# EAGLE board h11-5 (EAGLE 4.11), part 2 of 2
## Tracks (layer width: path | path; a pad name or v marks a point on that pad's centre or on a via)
+12V  (via drill 0.61)
  Top 0.635: v21.59,97.79 24.13,101.6 v31.75,101.6 | 174.63,109.22 176.53,107.31 176.53,100.33 IC24.14 | 174.63,109.22 176.53,111.12 176.53,114.94 178.44,116.84 187.33,116.84 R3.2 | Q5.3 174.63,109.22 | v182.88,49.53 195.58,49.53 198.12,52.07 C16.+ 198.12,123.19 189.87,123.19 R4.2
  Bottom 0.635: EDGE$.BD2 20.96,83.82 22.86,85.72 22.86,96.52 v21.59,97.79 | v31.75,101.6 31.75,129.54 45.72,129.54 | 109.22,129.54 187.33,129.54 R3.2 R4.2 | 109.22,129.54 45.72,129.54 | 45.72,129.54 C18.+ | R11.1 Q5.3 | 109.22,129.54 C17.+ | R24.1 R22.1 182.88,64.77 v182.88,49.53
-12V
  Bottom 0.635: W30.2 C8.- D5.A 184.15,97.79 184.15,87.63 | CL3.1 179.07,5.08 179.07,17.78 180.34,20.32 180.34,33.02 181.61,33.02 181.61,43.18 185.42,46.99 | 185.42,46.99 185.42,53.34 184.15,55.24 184.15,65.41 185.42,68.58 185.42,80.01 184.15,81.28 184.15,87.63 | 184.15,87.63 R2.2 | 185.42,46.99 CL2.2
-12V_EIA
  Top 0.406: W30.1 177.8,88.9 171.45,88.9 170.18,90.17 170.18,91.44 168.91,92.71 168.91,100.33 IC24.1
A1R
  Top 0.406: IC18.5 IC18.10 139.7,45.72 139.7,41.91 125.73,41.91 124.46,40.64 IC19.9 | IC12.3 114.3,19.05 116.84,16.51 IC12.11
  Bottom 0.406: IC12.11 116.84,16.51 116.84,25.4 119.38,27.94 IC19.9
A1R\  (via drill 0.61)
  Top 0.406: v73.66,35.56 74.93,36.2 81.28,36.2 83.82,37.47 88.27,37.47 89.54,36.83 96.52,36.83 99.06,39.37 v107.95,39.37 110.49,40.64 IC19.8 | IC26.13 135.26,97.79 133.35,101.6 127,101.6 127,99.06 123.19,99.06 119.38,93.98 113.03,93.98 | v111.76,93.98 113.03,93.98 | 113.03,93.98 114.3,93.98
  Bottom 0.406: IC10.9 69.85,11.43 69.85,16.51 76.2,20.32 76.2,24.13 76.2,33.02 v73.66,35.56 | v107.95,39.37 107.95,60.96 109.22,64.77 109.22,72.39 107.95,73.66 107.95,86.36 111.76,87.63 v111.76,93.98
A2R  (via drill 0.61)
  Top 0.406: IC18.9 134.62,43.18 132.08,44.45 123.19,44.45 121.92,43.18 IC19.10 | v121.92,54.61 107.32,54.61 106.05,55.88 100.97,55.88 98.43,53.34 92.71,53.34 91.44,52.07 85.09,52.07 83.19,55.88 78.11,55.88 73.66,53.34 64.77,53.34 63.5,52.07 IC8.1
  Bottom 0.406: v121.92,54.61 121.92,43.18 IC19.10 116.84,43.18 116.84,27.94 115.57,26.67 115.57,15.24 116.84,13.97 118.11,13.97 | 118.11,13.97 118.75,13.97 | 118.11,13.97 IC12.10
A2R\
  Top 0.406: IC19.11 121.29,45.72 121.92,48.26 IC18.4
  Bottom 0.406: IC19.11 115.57,45.72 115.57,36.83 114.3,35.56 114.3,16.51 113.03,16.51 | 113.03,16.51 112.4,16.51 | IC12.4 113.03,16.51
A3
  Bottom 0.406: IC5.15 A3.2 R32.2
A4
  Bottom 0.406: IC5.23 A4.2 R31.2
A5
  Bottom 0.406: R29.2 A5.2 IC5.17
A6
  Bottom 0.406: IC5.19 A6.2 R28.2
A7
  Bottom 0.406: IC5.21 A7.2 R27.2
A8
  Bottom 0.406: A8.2 R26.2 IC5.9
A9
  Bottom 0.406: IC5.7 R25.2 A9.2
A10
  Bottom 0.406: A10.2 R23.2 IC5.5
A11
  Bottom 0.406: A11.2 R21.2 IC5.3
A12
  Bottom 0.406: A12.2 R19.2
  Bottom 0.635: R19.2 IC5.1
AMTCH  (via drill 0.61)
  Top 0.406: IC5.13 75.57,99.06 v74.93,98.42 | v88.9,12.7 80.65,12.7 78.74,15.24 72.39,15.24 | 72.39,15.24 64.77,15.24 63.5,16.51 IC10.4 | 72.39,15.24 R41.1
  Bottom 0.406: v88.9,12.7 87.63,13.97 87.63,36.2 83.82,40.01 83.82,81.28 82.55,82.55 82.55,87.63 74.93,93.98 v74.93,98.42
BBS7\  (via drill 0.61)
  Top 0.406: IC2.11 33.02,7.62 21.59,7.62 19.05,10.16 19.05,26.67 19.69,27.94 19.69,38.1 23.5,38.1 23.5,41.91 v22.23,42.55
  Bottom 0.406: EDGE$.AP2 7.62,41.91 v22.23,42.55
BDAL0\
  Top 0.406: IC3.11 48.26,74.93 46.36,73.03 31.12,73.03 31.12,76.2 29.21,77.47 IC4.9
  Bottom 0.406: EDGE$.AU2 26.04,54.61 26.04,59.69 27.94,61.59 27.94,72.39 24.13,72.39 24.13,77.47 IC4.9
BDAL1\
  Top 0.406: IC3.13 46.99,80.01 45.72,81.28 30.48,81.28 29.21,82.55 IC4.7
  Bottom 0.406: EDGE$.AV2 24.77,58.42 24.77,60.96 26.67,62.87 26.67,71.12 22.86,71.12 22.86,82.55 IC4.7
BDAL2\  (via drill 0.61)
  Top 0.406: v21.59,86.36 24.13,81.28 29.21,81.28 31.75,77.47 IC4.12 36.83,77.47 40.64,80.01 IC3.8
  Bottom 0.406: v21.59,86.36 16.82,86.69 7.62,87 EDGE$.BE2
BDAL3\  (via drill 0.61)
  Top 0.406: v21.59,88.9 24.13,83.82 30.48,83.82 31.75,82.55 IC4.14 36.83,82.55 40.64,85.09 IC3.6
  Bottom 0.406: v21.59,88.9 16.79,89.89 7.62,90.17 EDGE$.BF2
BDAL4\  (via drill 0.61)
  Top 0.406: v21.59,91.44 24.13,88.9 29.21,88.9 31.75,87.63 IC4.16 36.83,87.63 40.64,90.17 IC3.4
  Bottom 0.406: v21.59,91.44 16.82,93.04 7.62,93.34 EDGE$.BH2
BDAL5\  (via drill 0.61)
  Top 0.406: v21.59,93.98 29.21,93.98 31.12,92.71 IC4.18
  Bottom 0.406: v21.59,93.98 16.84,96.19 7.62,96.52 EDGE$.BJ2 | IC4.18 36.83,92.71 40.64,95.25 IC3.2
BDAL6\
  Top 0.406: IC3.15 49.53,85.09 44.45,88.9 40.64,88.9 36.83,86.36 31.75,86.36 29.21,87.63 IC4.5
  Bottom 0.406: IC4.5 24.13,87.63 24.13,99.06 23.83,99.36 7.62,99.06 EDGE$.BK2
BDAL7\
  Top 0.406: IC3.17 46.36,90.17 45.09,91.44 29.85,91.44 29.21,92.71 IC4.3
  Bottom 0.406: IC4.3 29.21,92.71 29.21,99.06 26.67,101.6 17.78,101.6 15.57,102.54 7.62,102.87 EDGE$.BL2
BDAL8\  (via drill 0.61)
  Top 0.406: v22.86,105.41 29.21,105.41 31.75,104.14 IC1.11
  Bottom 0.406: EDGE$.BM2 22.53,105.74 v22.86,105.41
BDAL9\
  Bottom 0.406: EDGE$.BN2 26.34,108.89 IC1.8
BDAL10\
  Bottom 0.406: EDGE$.BP2 23.19,112.09 25.4,114.3 IC1.6
BDAL11\
  Bottom 0.406: EDGE$.BR2 21.26,115.24 25.4,119.38 IC1.4
BDAL12\
  Bottom 0.406: EDGE$.BS2 19.36,118.42 25.4,124.46 IC1.2
BDAL15\  (via drill 0.61)
  Top 0.406: v19.05,120.65 19.05,100.33 16.51,98.42 16.51,78.74 v17.15,78.11 | IC9.11 48.26,16.51 45.72,17.78 29.85,17.78 29.85,25.4 25.4,25.4 24.77,26.04 24.77,32.38 26.04,34.29 26.04,45.72 22.86,48.9 v22.86,63.5
  Bottom 0.406: v22.86,63.5 22.86,64.77 17.78,68.58 17.78,77.47 v17.15,78.11 | EDGE$.BV2 19.05,128.27 v19.05,120.65
BDCOK
  Top 0.406: IC1.13 31.75,109.22 29.21,107.95 20.96,107.95 20.96,100.33 17.78,97.79 17.78,83.82 19.05,81.28 19.05,73.66 7.62,73.66
  Top 0.635: EDGE$.BA1 7.62,73.66
BDIN\
  Bottom 0.406: IC2.8 24.77,13.97 24.77,20.32 22.86,22.86 7.62,22.86 EDGE$.AH2
BDMG
  Bottom 0.406: EDGE$.AS2 16.51,48.26 16.51,45.72 7.62,45.72 EDGE$.AR2
BDOUT\  (via drill 0.61)
  Top 0.406: IC2.13 32.39,13.97 29.85,12.7 22.86,12.7 v20.96,10.79
  Bottom 0.406: v20.96,10.79 15.24,16.51 7.62,16.51 EDGE$.AE2
BHALT\
  Top 0.406: H1.1 19.05,42.55 7.62,41.91
  Top 0.635: EDGE$.AP1 7.62,42.19 7.62,41.91
BIAKI\
  Bottom 0.406: EDGE$.AM2 19.05,35.56 19.05,25.4 22.86,25.4 IC2.2
BIAKO\  (via drill 0.61)
  Top 0.406: IC9.3 39.37,19.05 38.1,20.32 31.75,20.32 v31.75,34.29 | R34.2 20.96,15.24 20.96,35.56 R35.2
  Bottom 0.406: v31.75,34.29 25.4,34.29 25.4,36.83 R35.2 19.05,36.83 17.78,39.37 7.62,39.37 EDGE$.AN2
BINIT\
  Bottom 0.406: EDGE$.AT2 20.32,52.07 20.32,47.62 27.94,41.27 33.66,41.27 36.2,38.73 36.2,19.05 IC2.15
BIRQ4\  (via drill 0.61)
  Top 0.406: IC9.8 47.63,8.89 45.09,10.16 38.74,10.16 37.47,8.89 37.47,6.35 21.59,6.35 17.78,10.16 v17.78,30.48
  Bottom 0.406: EDGE$.AL2 16.51,31.75 v17.78,30.48
BRPLY
  Top 0.406: IC14.6 145.42,11.43 142.24,8.89 142.24,5.71 107.95,5.71 107.95,11.43 IC11.9 90.17,11.43 87.63,10.16 65.41,10.16 62.23,15.24 57.15,15.24 52.07,12.7 47.63,12.7 46.36,13.97 IC9.5
  Bottom 0.406: IC11.9 IC11.10
BRPLY\  (via drill 0.61)
  Top 0.406: IC9.6 38.1,11.43 36.83,10.16 v23.5,10.16
  Bottom 0.406: v23.5,10.16 23.5,19.68 22.86,20.32 7.62,20.32 EDGE$.AF2
BSYNC\
  Bottom 0.406: EDGE$.AJ2 16.51,26.04 17.78,26.04 17.78,24.13 IC2.4
BUF  (via drill 0.61)
  Top 0.406: IC6.15 64.77,77.47 62.87,76.2 55.88,76.2 v54.61,74.93 | IC26.11 134.62,92.71 132.08,93.98 125.1,93.98 122.56,90.81 100.97,90.81 99.06,90.17 95.89,90.17 94.62,91.44 90.81,91.44 90.17,90.81 57.15,90.81 v55.88,90.17
  Bottom 0.406: IC7.15 50.8,52.07 52.07,53.34 52.07,55.88 50.8,57.15 50.8,71.12 v54.61,74.93 54.61,82.55 55.88,83.82 v55.88,90.17
BUF\  (via drill 0.61)
  Top 0.406: IC8.15 69.85,49.53 71.12,50.8 101.6,50.8 103.51,52.07 v124.46,52.07 | IC21.8 132.72,62.23 132.08,63.5 127.64,63.5 v124.46,62.23
  Bottom 0.406: v124.46,52.07 v124.46,62.23 | IC8.15 69.85,49.53 69.85,46.99 72.39,46.99 72.39,36.83 77.47,36.83 77.47,19.05 71.12,15.24 71.12,8.89 IC10.8
BUFDIN  (via drill 0.61)
  Top 0.406: v53.34,30.48 53.98,31.11 76.84,31.11 78.11,32.38 85.73,32.38 87.63,33.66 110.49,33.66 112.4,34.92 139.7,34.92 v140.97,35.56
  Bottom 0.406: v53.34,30.48 53.34,19.05 IC9.12 | v140.97,35.56 140.97,52.07 139.7,53.34 139.7,67.31 IC21.10
BUSY
  Top 0.406: IC24.8 180.34,85.09 182.88,87.63 182.88,92.71 184.79,95.25 191.14,95.25 192.41,96.52 SV1.10
CLK0  (via drill 0.61)
  Top 0.406: IC20.17 87,46.99 v87.63,47.62 | IC20.40 v87.63,87.63 | v79.38,107.95 91.44,107.95 91.44,102.87 102.87,102.87 105.41,105.41 105.41,121.92 135.89,121.92 135.89,116.2 142.88,116.2 142.88,109.86 IC27.10 155.58,109.86 155.58,107.31 163.83,107.31 163.83,92.08 163.2,90.81 163.2,85.09 IC25.8
  Bottom 0.406: v87.63,87.63 v87.63,47.62 | v79.38,107.95 80.01,106.68 80.01,96.52 85.09,92.08 92.08,92.08 95.25,89.53 IC20.40
CTS
  Top 0.406: IC23.13 177.8,74.93 177.8,78.74 188.6,78.74 191.77,83.82 SV1.15
  Bottom 0.406: SV1.15 SV1.14
CTS\
  Top 0.406: IC23.11 172.72,69.85 170.18,68.58 163.83,68.58 161.29,71.12 154.31,71.12 151.77,73.66 141.61,73.66 139.07,71.12 135.26,71.12 133.35,67.31 IC21.5
DIN\  (via drill 0.61)
  Top 0.406: IC4.1 29.21,97.79 31.75,95.25 IC4.19 37.47,95.25 39.37,96.52 66.68,96.52 67.95,95.25 90.17,95.25 93.98,99.06 106.05,99.06 109.86,92.08 114.94,92.08 | v140.97,92.08 139.07,93.98 134.62,93.98 132.08,95.25 IC26.3 124.46,95.25 121.92,92.08 114.94,92.08 | 114.94,92.08 114.3,92.08 | v142.88,64.77 IC21.9
  Bottom 0.406: v142.88,64.77 142.88,72.39 140.97,74.3 v140.97,92.08
DR0  (via drill 0.61)
  Top 0.406: v91.44,41.91 IC20.19 | IC8.14 76.2,46.99 v77.47,48.26
  Bottom 0.406: v77.47,48.26 77.47,43.18 78.74,41.91 IC20.19 | IC11.12 93.98,19.05 93.98,26.67 92.71,27.94 92.71,40.64 v91.44,41.91
DSR  (via drill 0.61)
  Top 0.406: IC21.4 127,69.85 123.83,66.67 106.05,66.67 106.05,63.5 v73.66,63.5 | IC8.2 63.5,49.53 64.77,48.26 v72.39,48.26
  Bottom 0.406: v73.66,63.5 73.66,54.61 72.39,52.07 v72.39,48.26
DSR\
  Top 0.406: IC23.8 172.09,62.23 170.18,66.04 146.05,66.04 143.51,63.5 134.62,63.5 132.08,64.77 IC21.6
DSREIA
  Top 0.406: IC23.10 177.8,67.31 177.8,69.85 190.5,69.85 190.5,77.47 191.77,78.74 SV1.17
EPS
  Top 0.406: IC20.39 98.43,85.09 99.06,84.45 EPS.2
FE0
  Top 0.406: IC20.14 78.11,54.61 73.66,52.07 71.12,52.07 69.85,50.8 58.42,50.8 55.25,53.34 39.37,53.34 38.74,53.98 34.29,53.98 34.29,42.55 Q1.2
GND  (via drill 0.61, 0.81 pad 1.27)
  Top 0.635: EDGE$.BT1 14.91,121.59 16.6,121.58 | 16.6,121.58 21.34,127 IC1.1 28.7,127 31.07,124.46 IC1.19 40.64,124.46 C18.- 40.64,128.27 57.15,128.27 | 16.6,121.58 16.6,105.74 | 16.6,105.74 EDGE$.BM1 | 16.6,105.74 v16.6,104.14 | v24.13,68.58 24.13,74.93 IC4.10 29.21,74.93 29.21,71.12 v30.48,70.48 33.66,69.22 V3.1 | 57.15,128.27 57.15,124.46 A12.1 | V7.1 V6.1 | 15.88,26.67 EDGE$.AJ1 | 15.88,26.67 15.88,36.2 7.62,36.2 EDGE$.AM1 | IC25.4 IC25.11 | IC9.7 41.91,6.99 59.69,6.99 | 59.69,6.99 72.39,6.99 74.93,8.89 IC11.7 | 59.69,6.99 IC10.7 | IC15.7 166.37,6.35 149.86,6.35 | 149.86,6.35 146.05,6.35 v144.78,7.62 | 149.86,6.35 IC14.7 | v17.78,6.35 16.51,7.62 16.51,26.67 15.88,26.67 | NB1.1 120.65,81.92 121.29,81.28 C20.- | C17.- 114.3,128.27 57.15,128.27 | IC16.7 168.91,39.37 171.45,36.83 185.42,36.83 185.42,34.29 193.04,34.29 193.04,35.56 IC28.4 196.85,35.56 C12.2 201.93,30.48 201.93,48.26 C16.- | IC7.14 46.36,49.53 v45.09,48.26 | IC7.11 51.44,41.91 52.71,40.64 55.88,40.64 57.15,41.91 IC8.5
  Bottom 0.635: v16.6,104.14 IC1.10 28.58,104.14 | EDGE$.BC2 20.32,80.34 20.32,68.58 v24.13,68.58 | 45.72,74.93 IC3.10 | 62.23,62.23 V4.1 62.23,46.99 | 45.72,74.93 V3.1 41.91,69.22 41.91,57.78 46.36,57.78 46.36,49.53 v45.09,48.26 45.09,36.83 44.45,36.83 | A12.1 A11.1 A10.1 A9.1 A8.1 58.42,101.6 | A4.1 A7.1 A6.1 A5.1 A3.1 107.95,104.14 v107.95,113.03 118.11,113.03 | 58.42,101.6 IC5.11 IC5.12 71.12,97.79 | 71.12,97.79 71.12,95.25 77.47,90.17 77.47,82.55 IC20.3 | Q1.1 38.74,36.83 IC7.8 44.45,36.83 | IC3.19 58.42,95.25 58.42,101.6 | C18.- C15.- 40.64,97.79 IC3.1 45.72,97.79 45.72,74.93 | 62.23,62.23 IC6.8 | 62.23,86.36 62.23,62.23 | 62.23,86.36 V5.1 | 62.23,86.36 62.23,97.79 71.12,97.79 | IC1.1 28.58,127 28.58,104.14 | V7.1 30.48,58.42 v30.48,70.48 | 26.67,6.35 v17.78,6.35 | 26.67,6.35 41.91,6.35 IC9.7 44.45,8.89 44.45,33.02 | 26.67,6.35 IC2.10 30.48,8.89 30.48,29.21 | 30.48,29.21 IC2.19 | 30.48,29.21 30.48,31.75 IC2.1 25.4,31.75 R35.1 | C6.2 C17.- | C6.2 118.11,113.03 | 44.45,36.83 44.45,33.02 | IC10.7 62.23,8.89 62.23,34.29 | 62.23,34.29 IC8.8 | 62.23,46.99 62.23,41.91 | 62.23,41.91 62.23,34.29 | 82.55,49.53 82.55,39.37 86.36,35.56 86.36,8.89 IC11.7 83.82,6.99 109.22,6.99 109.22,8.89 | 82.55,49.53 IC20.16 | IC19.12 116.84,48.26 116.84,62.23 C11.- NP.1 TSB.1 NB2.1 NB1.1 EPS.1 116.21,87.63 116.21,98.42 C5.2 118.11,113.03 | 109.22,8.89 109.22,20.32 | 109.22,20.32 109.22,21.59 IC12.2 IC12.1 | 109.22,8.89 IC12.7 111.76,6.99 129.54,6.99 | 129.54,6.99 143.51,6.99 v144.78,7.62 | 129.54,6.99 IC13.7 132.08,8.89 132.08,33.02 129.54,35.56 IC18.7 132.08,40.64 132.08,62.23 | 132.08,62.23 IC21.7 | 132.08,81.28 132.08,62.23 | 132.08,81.28 C20.-
  Bottom 0.635: 132.08,81.28 132.08,85.09 IC26.7 127.64,85.09 127.64,102.87 135.89,102.87 IC27.8 140.97,107.31 140.97,128.27 | 140.97,128.27 118.11,128.27 C6.2 | 140.97,128.27 149.86,128.27 FR1.2 | 154.94,124.46 FR0.2 | FR0.2 FR1.2 | 154.94,124.46 154.94,106.68 FR3.2 FR2.2 149.86,104.14 146.05,102.23 146.05,95.25 IC25.3 IC25.4 151.13,92.71 151.13,85.09 | 151.13,85.09 IC25.7 | 151.77,62.23 151.77,78.74 151.13,79.38 C10.- 151.13,85.09 | 151.77,62.23 IC22.7 | 151.77,39.37 IC17.7 | 151.77,62.23 151.77,39.37 | 151.77,39.37 151.77,8.89 IC14.7 | 184.15,119.38 D6.C 184.15,123.19 Q6.3 Q4.1 165.1,124.46 154.94,124.46 | 184.15,119.38 184.15,116.84 177.8,116.84 176.53,115.57 176.53,111.76 177.8,110.49 C8.+ 168.91,107.95 168.91,97.79 IC24.13 IC24.12 168.91,95.25 168.91,85.09 | 168.91,85.09 168.91,62.23 | 168.91,62.23 IC23.7 | IC16.7 168.91,39.37 | 168.91,62.23 168.91,39.37 | IC15.7 168.91,8.89 C9.- 168.91,39.37 | 187.96,81.28 C3.2 C4.2 187.96,68.58 185.42,64.77 185.42,58.42 SV1.25 SV1.24 | 187.96,81.28 C1.2 | 198.12,81.28 SV1.16 187.96,81.28 | 198.12,81.28 200.66,81.28 200.66,60.96 202.57,58.42 202.57,48.26 C16.- | 198.12,81.28 198.12,119.38 SV1.1 184.15,119.38 | FR0.2 FR1.2 | C2.2 162.56,85.09 IC24.7 168.91,85.09 | C13.- C19.2 109.22,20.32 | 28.58,104.14 28.58,101.6 30.48,99.06 30.48,71.12 | IC25.10 IC25.11 160.02,92.71 | 160.02,92.71 160.66,92.71 | 160.02,92.71 C14.2 | 82.55,49.53 82.55,80.01 IC20.4 | 44.45,33.02 R12.1 | 62.23,41.91 IC8.5 | 62.23,46.99 IC8.3
ICSR  (via drill 0.61)
  Top 0.406: IC22.3 146.69,72.39 146.69,69.85 142.24,69.85 139.07,66.04 128.27,66.04 v125.73,64.77
  Bottom 0.406: 120.65,8.89 120.02,8.89 | 120.65,8.89 124.46,8.89 124.46,20.32 125.73,20.32 | 125.73,20.32 127,20.32 128.27,19.05 | 128.27,19.05 128.91,19.05 | 125.73,20.32 v125.73,64.77 | IC12.8 120.65,8.89 | 128.27,19.05 IC13.3
IIAKI\  (via drill 0.61)
  Top 0.406: IC15.13 177.8,21.59 177.8,4.45 78.74,4.45 v78.74,5.08 | v177.8,30.48 167.01,30.48 164.47,27.94 139.7,27.94 v138.43,27.3
  Bottom 0.406: v78.74,5.08 78.74,16.51 IC11.4 | IC15.13 177.8,21.59 v177.8,30.48 | IC18.12 139.7,50.8 139.7,40.64 138.43,38.1 v138.43,27.3
INIT\  (via drill 0.61)
  Top 0.406: v43.18,27.94 45.09,27.3 52.71,27.3 54.61,26.04 56.52,26.04 58.42,27.3 78.74,27.3 80.01,28.57 87.63,28.57 89.54,29.84 127,29.84 v129.54,30.48 | IC15.4 v161.29,16.51 160.02,17.78 153.67,17.78 151.13,20.32 141.61,20.32 140.34,21.59 IC13.13 134.62,21.59 133.35,24.13 IC13.1 | IC17.4 151.13,46.99 153.67,44.45 IC17.10 160.02,44.45 v162.56,43.18 | IC22.13 160.02,74.93 160.66,72.39 v162.56,72.39
  Bottom 0.406: v43.18,27.94 43.18,29.21 39.37,29.21 38.1,27.94 38.1,17.78 36.83,16.51 IC2.14 | v162.56,72.39 163.83,71.12 163.83,57.15 162.56,55.88 v162.56,43.18 161.93,40.01 161.93,34.92 161.29,33.66 v161.29,16.51 | v129.54,30.48 IC13.1
IRQ  (via drill 0.61)
  Top 0.406: v164.47,33.66 146.05,33.66 143.51,32.38 115.57,32.38 112.4,31.11 88.9,31.11 87,29.84 79.38,29.84 78.11,28.57 55.88,28.57 v54.61,27.94
  Bottom 0.406: IC9.10 IC9.9 53.34,11.43 54.61,12.7 v54.61,27.94 | v164.47,33.66 164.47,40.64 165.74,41.91 IC16.6
MDIN
  Top 0.406: IC16.11 176.53,46.99 176.53,43.18 165.1,43.18 161.93,40.64 143.51,40.64 140.97,49.53 132.72,49.53 131.45,50.8 IC18.3
MDIN\  (via drill 0.61)
  Top 0.406: v121.92,93.98 125.73,97.79 IC26.2 | IC10.3 62.23,19.05 64.77,20.32 69.22,20.32 71.12,17.78 86.36,17.78 88.9,20.32 93.98,20.32 99.7,17.78 114.3,17.78 116.84,15.24 125.73,15.24 127.64,20.32 131.45,20.32 132.72,17.78 142.24,17.78 143.51,19.05 IC14.3 | IC16.12 171.45,49.53 169.55,50.8 164.47,50.8 159.39,57.15 v146.05,57.15 145.42,56.52 140.97,56.52 139.07,58.42 v122.56,58.42
  Bottom 0.406: v121.92,93.98 120.65,92.71 120.65,62.23 122.56,60.33 v122.56,58.42 | v146.05,57.15 146.05,54.61 144.78,52.07 144.78,36.83 146.05,35.56 146.05,19.05 IC14.3
MDOUT  (via drill 0.61)
  Top 0.406: IC18.11 133.35,48.26 132.08,46.99 124.46,46.99 v124.46,45.72 | IC12.12 124.46,19.05 v124.46,24.13
  Bottom 0.406: v124.46,24.13 v124.46,45.72
MDOUT\
  Top 0.406: IC14.5 144.15,13.97 139.7,10.16 127,10.16 125.73,11.43 IC12.9 | IC12.5 109.22,13.97 109.22,16.51 97.16,16.51 93.98,17.78 88.9,17.78 86.36,15.24 81.28,15.24 80.01,16.51 IC10.11
  Bottom 0.406: 113.03,13.97 112.4,13.97 | 113.03,13.97 114.3,13.97 116.84,11.43 IC12.9 121.92,11.43 121.92,21.59 120.65,21.59 | 120.65,21.59 120.02,21.59 | IC12.5 113.03,13.97 | 120.65,21.59 IC12.13
MIRDY\
  Top 0.635: IC17.12 158.75,49.53 160.02,45.72 162.56,45.72 163.83,44.45 IC16.5
  Bottom 0.406: IC17.12 160.02,49.53 160.02,21.59 159.39,20.32 159.39,8.89 IC14.8
MXRDY\  (via drill 0.61)
  Top 0.406: IC16.4 163.83,46.99 161.29,50.8 153.67,50.8 152.4,52.07 IC17.2 | IC14.12 160.02,19.05 160.66,19.68 v162.56,19.68
  Bottom 0.406: IC16.4 164.47,46.99 164.47,42.55 163.2,40.01 163.2,35.56 162.56,33.66 v162.56,19.68
MYIO\  (via drill 0.61)
  Top 0.406: IC19.2 109.22,55.88 106.68,57.78 99.7,57.78 97.79,55.88 92.71,55.88 91.44,53.98 86.36,53.98 83.82,58.42 76.84,58.42 73.03,56.52 67.95,56.52 v66.04,54.61
  Bottom 0.406: v66.04,54.61 63.5,52.07 63.5,7.62 57.15,7.62 57.15,11.43 IC10.6
MYIOR  (via drill 0.61)
  Top 0.406: v102.87,26.67 101.6,27.3 90.81,27.3 88.9,26.04 81.28,26.04 79.38,21.59 v74.93,21.59
  Top 0.635: IC10.2 IC10.13
  Bottom 0.406: IC10.13 v74.93,21.59 | v102.87,26.67 109.22,35.56 109.22,58.42 110.49,58.42 | 110.49,58.42 111.13,58.42 | 110.49,58.42 IC19.1
N$1
  Bottom 0.406: C2.1 IC23.2
N$2
  Bottom 0.406: IC27.14 152.4,120.02 FR0.1
N$3
  Bottom 0.406: H1.2 Q1.3
N$4
  Bottom 0.406: IC27.13 149.23,117.47 FR1.1
N$5
  Bottom 0.406: IC27.12 149.23,114.94 FR2.1
N$6
  Bottom 0.406: IC27.11 152.4,112.39 FR3.1
N$7
  Top 0.406: IC11.3 72.39,19.05 69.85,22.86 46.99,22.86 44.45,21.59 IC9.2
N$9
  Bottom 0.406: IC27.7 134.62,109.86 R9.1 K1.1 125.73,106.68 C5.1
N$10
  Bottom 0.406: IC27.6 134.62,112.39 R9.2 134.62,119.38 K1.2 125.73,119.38 C6.1
N$11
  Bottom 0.406: CL4.1 CL3.2 190.5,5.08 186.69,8.89 | 186.69,13.97 Q2.3 | 186.69,12.7 186.69,13.97 | 186.69,8.89 186.69,12.7 | 186.69,12.7 Q3.D | 186.69,13.97 Q3.G | D2.A 186.69,8.89
N$12
  Bottom 0.406: 92.71,8.89 92.08,8.89 | 92.71,8.89 R33.1 | IC11.8 92.71,8.89
N$13
  Bottom 0.406: IC29.6 199.39,27.94 R7.2
N$15
  Bottom 0.406: R7.1 199.39,22.86 IC29.4 195.58,16.51 Q2.2 184.15,16.51 Q3.S
N$16
  Bottom 0.406: IC29.1 187.33,27.94 R8.2
N$19
  Bottom 0.406: C4.1 179.07,72.39 176.53,71.12 176.53,64.77 IC23.9
N$20
  Bottom 0.635: D5.C 181.61,111.76 | 181.61,111.76 181.61,114.3 C7.- | 181.61,111.76 D6.A
N$22
  Bottom 0.635: Q6.1 172.72,118.11 C7.+ Q5.1
N$23  (via drill 0.61)
  Top 0.406: R33.2 106.68,6.99 76.2,6.99 74.3,5.71 39.37,5.71 v39.37,7.62
  Bottom 0.406: R33.2 C19.1 | v39.37,7.62 39.37,16.51 IC9.4
N$25
  Bottom 0.406: C3.1 176.53,72.39 IC23.12
N$26
  Bottom 0.635: Q6.2 170.18,120.65 Q4.3 160.02,118.11 | 160.02,118.11 R11.2 | 160.02,118.11 160.02,111.76 Q5.2
N$27
  Bottom 0.406: R2.1 D3.A 179.07,93.98 R1.1
N$28
  Top 0.406: IC28.2 180.34,38.1 CL2.1
  Bottom 0.406: CL2.1 R5.1 D1.A CL1.1
N$29
  Bottom 0.406: R4.1 189.87,108.58 186.69,105.41 Q7.2 184.15,101.6 181.61,104.14 ZD4.C
N$30  (via drill 0.61)
  Top 0.406: v194.31,53.34 191.77,54.61 176.53,54.61 176.53,55.88 166.37,55.88 IC16.1
  Bottom 0.406: IC28.5 C12.1 R6.2 194.31,44.45 v194.31,53.34
N$31
  Bottom 0.406: Q7.1 184.15,106.68 187.33,109.86 R3.1
N$32
  Bottom 0.406: IC25.6 IC25.5
N$135  (via drill 0.61)
  Top 0.406: v128.27,80.01 128.91,79.38 v142.24,79.38
NB1
  Top 0.406: IC20.38 98.43,82.55 99.06,81.92 NB1.2
NB2
  Top 0.406: IC20.37 98.43,80.01 99.06,79.38 NB2.2
NOEOT\  (via drill 0.61)
  Top 0.406: IC25.13 153.67,97.79 151.13,96.52 v142.24,96.52
  Bottom 0.406: v142.24,96.52 139.7,93.98 139.7,74.93 IC21.13
NOIAKI  (via drill 0.61)
  Top 0.406: v55.88,56.52 41.91,56.52 IC7.1 | IC26.12 134.62,95.25 132.08,100.33 IC26.1 | IC11.6 70.49,11.43 70.49,13.97 IC10.10
  Bottom 0.406: IC6.1 55.88,80.01 v55.88,56.52 55.88,31.75 57.15,30.48 57.15,13.97 55.88,11.43 55.88,5.08 64.77,5.08 64.77,13.97 IC10.10 | IC11.6 81.92,11.43 81.92,5.71 146.69,5.71 146.69,16.51 147.32,16.51 | 147.32,16.51 149.23,16.51 | 147.32,16.51 144.78,16.51 144.78,34.29 143.51,35.56 143.51,57.15 144.78,58.42 144.78,66.04 144.15,67.31 144.15,73.66 143.51,74.93 143.51,97.79 140.34,97.79 138.43,95.25 IC26.12 | 147.32,16.51 IC14.4
NP
  Top 0.406: IC20.35 98.43,74.93 99.06,74.3 NP.2
PUMP
  Top 0.406: Q4.2 161.29,127 142.24,127 142.24,122.56 IC27.2
RB0  (via drill 0.61)
  Top 0.406: IC7.10 56.52,39.37 57.79,40.64 74.93,40.64 v75.57,41.27
  Bottom 0.406: v75.57,41.27 75.57,49.53 77.47,52.07 77.47,59.69 IC20.12
RB1  (via drill 0.61)
  Top 0.406: IC20.11 71.76,62.23 70.49,60.33 59.06,60.33 57.15,58.42 v54.61,58.42 | IC7.13 52.07,46.99 v54.61,50.8
  Bottom 0.406: v54.61,50.8 v54.61,58.42
RB2  (via drill 0.61)
  Top 0.406: IC6.3 62.87,74.93 64.77,76.2 70.49,76.2 71.12,76.83 73.66,76.83 74.3,75.56 v76.2,75.56
  Bottom 0.406: v76.2,75.56 76.2,66.04 77.47,64.77 IC20.10
RB3
  Top 0.406: IC6.6 62.87,67.31 64.77,66.04 69.85,66.04 73.03,68.58 76.2,68.58 78.11,67.31 IC20.9
RB4
  Top 0.406: IC20.8 82.55,69.85 82.55,66.04 72.39,66.04 69.85,64.77 IC6.10
RB5
  Top 0.406: IC6.13 69.85,72.39 70.49,71.75 76.84,71.75 78.11,72.39 IC20.7
RB6  (via drill 0.61)
  Top 0.406: IC20.6 82.55,74.93 82.55,71.12 78.74,71.12 76.2,69.85 72.39,69.85 71.12,68.58 58.42,68.58 54.61,63.5 v38.1,63.5
  Bottom 0.406: IC7.6 40.64,41.91 38.1,45.09 v38.1,63.5
RB7  (via drill 0.61)
  Top 0.406: IC20.5 78.11,77.47 78.11,74.3 76.2,73.03 70.49,73.03 69.85,73.66 55.88,73.66 55.25,73.03 49.53,73.03 46.99,71.75 41.91,71.75 v41.91,71.12
  Bottom 0.406: IC7.3 44.45,49.53 44.45,56.52 40.64,56.52 40.64,69.85 v41.91,71.12
RBS7
  Top 0.406: IC2.9 29.85,11.43 32.39,12.7 45.09,12.7 48.26,10.16 52.07,10.16 57.79,13.97 IC10.5
RBUF\
  Top 0.406: IC18.6 124.46,43.18 121.92,41.91 99.7,41.91 97.79,43.18 93.98,43.18 92.71,44.45 IC20.18
RDAL0  (via drill 0.61)
  Top 0.406: IC22.12 154.94,72.39 152.4,74.93 IC22.2 140.34,74.93 138.43,73.66 133.35,73.66 132.08,71.12 126.37,71.12 123.83,67.94 106.05,67.94 v104.14,66.04 90.17,66.04 82.55,78.74 56.52,78.74 52.71,76.2 47.63,76.2 45.72,77.47 IC3.9 | IC20.26 100.33,52.07 v104.14,53.34
  Bottom 0.406: v104.14,66.04 v104.14,53.34
RDAL1  (via drill 0.61)
  Top 0.406: v88.9,83.82 76.84,83.82 74.3,81.92 70.49,81.92 69.22,83.19 57.79,83.19 52.71,81.28 47.63,81.28 46.36,82.55 IC3.7 | IC19.7 100.97,43.18 99.06,45.09 v99.06,46.99
  Bottom 0.406: v88.9,83.82 88.9,58.42 92.71,54.61 IC20.27 97.79,54.61 99.06,53.34 v99.06,46.99
RDAL2  (via drill 0.61)
  Top 0.406: v90.17,81.28 75.57,81.28 74.3,80.64 69.85,80.64 68.58,81.92 58.42,81.92 52.71,77.47 IC3.12 | IC19.6 107.95,45.72 106.68,44.45 101.6,44.45 v100.33,45.72
  Bottom 0.406: v90.17,81.28 90.17,59.69 92.71,57.15 IC20.28 97.79,57.15 100.33,54.61 v100.33,45.72
RDAL3  (via drill 0.61)
  Top 0.406: IC5.14 v77.47,101.6 74.93,100.33 v67.31,100.33
  Bottom 0.406: IC3.14 53.34,82.55 53.34,92.08 59.69,92.08 59.69,100.33 v67.31,100.33 | v77.47,101.6 77.47,93.98 83.19,89.53 90.17,89.53 91.44,89.53 91.44,60.96 92.71,59.69 IC20.29
RDAL4  (via drill 0.61)
  Top 0.406: IC3.16 58.42,87.63 60.33,89.53 v93.35,89.53
  Bottom 0.406: IC5.22 77.47,121.92 77.47,105.41 78.74,102.87 78.74,95.25 85.09,90.81 92.08,90.81 v93.35,89.53 92.71,88.9 92.71,86.36 92.71,62.23 IC20.30
RDAL5  (via drill 0.61)
  Top 0.406: IC3.18 53.34,92.71 53.98,93.34 67.31,93.34 68.58,93.98 93.98,93.98 96.52,96.52 v97.79,96.52
  Bottom 0.406: IC5.16 83.82,106.68 83.82,99.06 86.36,96.52 v97.79,96.52 100.33,93.98 100.33,64.77 IC20.31
RDAL6  (via drill 0.61)
  Top 0.406: IC3.5 44.45,87.63 48.26,83.82 52.71,83.82 53.98,84.45 69.22,84.45 70.49,83.19 74.3,83.19 78.74,86.36 83.82,86.36 85.09,85.09 90.17,85.09 92.71,82.55 92.71,67.31 IC20.32 100.33,67.31 102.87,69.85 v123.19,69.85 | IC13.2 132.08,21.59 133.35,19.05 IC13.12
  Bottom 0.406: IC5.18 82.55,111.76 82.55,97.79 86.36,95.25 95.25,95.25 99.06,91.44 99.06,67.31 IC20.32 | v123.19,69.85 127,69.85 127,22.86 128.27,21.59 IC13.2
RDAL7  (via drill 0.61)
  Top 0.406: IC3.3 46.99,92.71 48.26,91.44 53.34,91.44 53.98,92.08 67.95,92.08 69.22,92.71 95.89,92.71 v96.52,92.08
  Bottom 0.406: IC5.20 81.28,116.84 81.28,97.16 86.36,93.98 94.62,93.98 v96.52,92.08 97.79,90.17 97.79,69.85 IC20.33
RDAL8
  Top 0.406: IC1.9 29.21,106.68 31.75,105.41 49.53,105.41 54.61,100.33 64.77,100.33 68.58,104.14 IC5.10
RDAL9
  Top 0.406: IC1.12 36.83,106.68 38.1,107.95 49.53,107.95 55.88,101.6 58.42,101.6 62.23,105.41 67.31,105.41 68.58,109.22 IC5.8
RDAL10
  Top 0.406: IC1.14 50.17,111.76 52.71,114.3 55.88,114.3 58.42,111.76 59.69,111.76 60.96,113.03 67.31,113.03 68.58,114.3 IC5.6
RDAL11
  Top 0.406: IC1.16 49.53,116.84 52.07,119.38 55.25,119.38 57.79,116.84 60.96,116.84 62.23,118.11 67.31,118.11 68.58,119.38 IC5.4
RDAL12
  Top 0.406: IC1.18 49.53,121.92 51.44,123.83 55.88,123.83 57.79,121.92 60.33,121.92 61.6,123.19 67.31,123.19 68.58,124.46 IC5.2
RDCOK  (via drill 0.61)
  Top 0.406: IC1.7 29.21,111.76 30.48,110.49 36.83,110.49 38.1,109.22 55.25,109.22 57.79,106.68 59.06,106.68 62.23,110.49 74.93,110.49 77.47,105.41 88.9,105.41 v88.9,101.6 104.14,101.6 107.32,104.78 139.7,104.78 140.97,106.68 140.97,114.94 IC27.5
  Bottom 0.406: 95.25,38.1 95.25,34.29 101.6,34.29 101.6,43.18 102.87,44.45 102.87,49.53 101.6,50.8 101.6,60.96 102.87,63.5 102.87,99.06 91.44,99.06 v88.9,101.6 | 95.25,38.1 95.25,38.73 | 95.25,38.1 IC20.21
RDIN  (via drill 0.61)
  Top 0.406: IC17.3 151.13,49.53 153.67,46.99 IC17.11 | v156.85,31.75 154.31,32.38 147.32,32.38 145.42,31.11 133.99,31.11 132.08,28.57 89.54,28.57 87.63,27.3 80.65,27.3 79.38,26.04 62.87,26.04 61.6,24.13 IC10.1 54.61,24.13 52.71,26.04 41.91,26.04 v40.64,26.67
  Bottom 0.406: IC17.11 158.75,46.99 158.75,34.29 v156.85,31.75 | v40.64,26.67 39.37,25.4 39.37,17.78 36.83,15.24 36.83,11.43 IC2.12
RDOUT
  Top 0.406: IC10.12 64.77,19.05 63.5,17.78 55.88,17.78 52.07,15.24 32.39,15.24 30.48,16.51 IC2.7
RDR+
  Bottom 0.406: D3.C 187.33,92.71 187.33,98.42 189.23,100.33 Q7.3 191.77,106.68 SV1.6
RDR-
  Bottom 0.406: SV1.9 189.23,99.06 R1.2
RIAKI  (via drill 0.61)
  Top 0.406: IC2.18 36.83,26.67 38.74,25.4 | 38.74,25.4 40.64,24.13 IC9.1 | v177.8,34.29 175.9,35.56 146.69,35.56 142.88,33.66 113.67,33.66 111.13,32.38 88.27,32.38 86.36,31.11 78.74,31.11 77.47,29.84 54.61,29.84 53.34,28.57 45.72,28.57 44.45,29.84 40.01,29.84 38.74,28.57 38.74,25.4 | IC18.1 133.35,55.88 134.62,54.61 146.05,54.61 147.32,55.88 158.75,55.88 165.1,48.26 168.28,48.26 171.45,44.45 IC16.10
  Bottom 0.406: IC16.10 175.26,44.45 177.8,41.91 v177.8,34.29
RIE  (via drill 0.61)
  Top 0.406: IC13.5 133.99,13.97 135.26,12.7 139.7,12.7 140.97,15.24 151.13,15.24 154.94,11.43 IC14.9 | v125.73,19.05 125.1,17.78 116.84,17.78 114.3,22.86 109.22,22.86 107.32,21.59 99.06,21.59 98.43,20.95 95.89,20.95 94.62,21.59 IC11.13 88.9,21.59 87,20.32 74.93,20.32 73.66,20.32 73.66,22.86 v74.93,24.13
  Bottom 0.406: IC8.11 71.12,39.37 71.12,25.4 74.93,25.4 v74.93,24.13 | IC13.5 125.73,13.97 v125.73,19.05
RINIT  (via drill 0.61)
  Top 0.406: IC2.5 23.5,24.77 23.5,33.02 24.77,34.92 24.77,43.81 20.32,47.62 20.32,82.55 19.05,84.45 19.05,95.89 24.13,95.89 24.13,99.06 32.39,99.06 34.29,100.97 51.44,100.97 54.61,98.42 67.95,98.42 69.85,96.52 89.54,96.52 93.35,100.33 114.3,100.33 118.11,97.79 v118.11,96.52
  Bottom 0.406: IC2.6 IC2.5 | v118.11,96.52 125.1,96.52 125.1,93.98 121.92,90.17 121.92,78.74 125.73,72.39 128.27,72.39 | 128.27,72.39 128.91,72.39 | 128.27,72.39 IC21.3
RIRQ
  Top 0.406: IC18.2 132.08,53.34 133.35,52.07 142.24,52.07 144.78,41.91 IC17.6
RIRQ\  (via drill 0.61)
  Top 0.406: v148.59,31.11 146.05,29.21 135.26,29.21 133.99,27.3 107.32,27.3 104.78,24.77 100.97,24.77 99.06,26.04 90.81,26.04 88.27,24.13 IC11.1
  Bottom 0.406: IC17.5 146.05,44.45 146.05,38.1 148.59,34.29 v148.59,31.11
RRDY
  Top 0.406: IC14.10 IC15.5
RRDYI
  Top 0.406: IC14.11 158.75,16.51 161.29,15.24 168.91,15.24 | 168.91,15.24 168.91,10.16 153.67,10.16 151.13,12.7 144.78,12.7 140.97,9.53 140.97,6.99 109.22,6.99 109.22,12.06 106.68,15.24 97.16,15.24 93.98,16.51 IC11.11 | IC15.3 167.64,19.05 168.91,17.78 168.91,15.24
RRUN\  (via drill 0.61)
  Top 0.406: ZD4.A v144.78,104.14 | IC21.11 139.7,69.85 141.61,71.75 v145.42,71.75
  Bottom 0.406: v144.78,104.14 144.78,77.47 146.05,76.2 146.05,71.75 | 146.05,71.75 146.05,64.77 | 146.05,64.77 147.32,64.77 | 146.05,71.75 v145.42,71.75 | 146.05,64.77 IC22.6
RSTOP\
  Top 0.406: IC22.1 144.15,77.47 142.88,76.2 133.35,76.2 132.08,77.47 IC21.1
RSYNC
  Bottom 0.406: IC2.16 IC2.17
RTS
  Top 0.406: SV1.8 190.5,101.6 186.06,97.16 184.15,97.16 181.61,94.61 177.8,94.61 176.53,92.71 IC24.11
  Bottom 0.406: SV1.8 SV1.7
RX+
  Bottom 0.406: CL1.2 R22.2 190.5,66.04 SV1.22
RX-
  Bottom 0.635: SV1.20 196.85,71.12 196.85,58.42 195.58,55.88 D1.C R5.2 190.5,50.8 190.5,48.26 191.77,46.99 191.77,40.64 IC28.1
RXCL
  Top 0.406: IC16.3 168.91,49.53 170.82,48.26 177.17,48.26 179.71,50.8 193.04,50.8 195.58,52.07 195.58,68.58 SV1.21
RXD  (via drill 0.61)
  Top 0.406: v143.51,59.69 189.23,59.69 191.77,63.5 SV1.23 | v76.2,60.96 107.32,60.96 107.32,65.41 123.83,65.41 127.64,68.58 132.72,68.58 134.62,72.39 IC21.12
  Bottom 0.406: v143.51,59.69 140.97,59.69 140.97,72.39 IC21.12 | v76.2,60.96 76.2,54.61 73.66,50.8 73.66,39.37 IC20.20
RXEIA
  Top 0.406: IC23.3 168.91,72.39 168.91,80.01 187.96,80.01 189.23,81.92 189.23,85.09 190.5,86.36 190.5,88.9 SV1.13
RXEIA\
  Top 0.406: IC23.1 166.37,81.28 184.79,81.28 184.79,84.45 187.33,87 187.33,91.44 SV1.12
SBRK  (via drill 0.61)
  Top 0.406: IC8.6 63.5,39.37 64.77,38.1 71.12,38.1 71.76,37.47 81.28,37.47 83.19,39.37 v91.44,39.37 | IC22.9 152.4,64.77 151.13,63.5 145.42,63.5 140.97,60.33 128.27,60.33 | 128.27,60.33 127.64,60.33 | 128.27,60.33 109.22,60.33 107.95,59.69 99.7,59.69 97.79,58.42 91.44,58.42 v88.9,55.88
  Bottom 0.406: v88.9,55.88 90.17,54.61 90.17,40.64 v91.44,39.37
SBRK\  (via drill 0.61)
  Top 0.406: IC26.10 139.7,90.17 142.24,88.9 v160.02,88.9
  Bottom 0.406: v160.02,88.9 160.02,62.23 IC22.8
START  (via drill 0.61)
  Top 0.406: IC25.12 158.75,95.25 158.75,92.71 158.75,91.44 144.78,91.44 142.24,90.17 139.7,91.44 125.73,91.44 v124.46,90.17
  Bottom 0.406: v124.46,90.17 124.46,83.82 127,82.55 127,74.93 IC21.2
SYNC\  (via drill 0.61)
  Top 0.406: IC2.3 29.21,26.67 29.21,36.2 33.02,36.2 34.29,34.92 v52.07,34.92 | IC19.13 IC19.4 109.22,50.8 105.41,48.26 92.71,48.26 90.17,45.72 55.88,45.72 v54.61,46.99
  Bottom 0.406: v54.61,46.99 52.07,43.18 v52.07,34.92
TDAL0  (via drill 0.61)
  Top 0.406: IC8.7 IC7.9 47.63,36.83 45.09,38.1 40.01,38.1 38.74,36.83 34.93,36.83 34.29,38.1 34.29,40.64 33.02,41.91 v33.02,46.99
  Bottom 0.406: IC4.11 34.29,69.22 33.02,66.67 v33.02,46.99
TDAL1  (via drill 0.61)
  Top 0.406: v34.29,59.69 35.56,58.42 v52.07,58.42
  Bottom 0.406: IC4.13 36.83,80.01 36.83,68.58 34.29,64.77 v34.29,59.69 | v52.07,58.42 53.34,57.15 53.34,53.34 52.07,52.07 52.07,45.72 50.8,44.45 IC7.12 48.26,44.45 47.63,43.18 47.63,34.92 R12.2
TDAL2
  Top 0.406: IC4.8 21.59,80.01 21.59,65.41 40.01,65.41 40.64,64.77 46.99,64.77 51.44,71.75 55.88,71.75 56.52,72.39 IC6.4
TDAL3  (via drill 0.61)
  Top 0.406: IC6.7 57.79,64.77 55.88,62.23 40.01,62.23 39.37,61.59 36.83,61.59 34.93,63.5 v24.77,63.5
  Bottom 0.406: v24.77,63.5 25.4,64.77 25.4,69.85 21.59,69.85 21.59,82.55 24.13,85.09 IC4.6
TDAL4  (via drill 0.61)
  Top 0.406: IC6.9 64.77,62.23 62.87,63.5 58.42,63.5 56.52,60.33 36.2,60.33 35.56,60.96 29.21,60.96 v28.58,59.69
  Bottom 0.406: IC4.4 29.21,90.17 29.21,60.96 v28.58,59.69
TDAL5  (via drill 0.61)
  Top 0.406: IC4.2 29.21,95.25 31.12,93.98 52.71,93.98 53.98,95.25 v66.04,95.25
  Bottom 0.406: v66.04,95.25 66.04,93.98 73.66,87.63 73.66,69.85 IC6.12
TDAL6
  Top 0.406: IC7.7 45.09,39.37 46.99,38.1 62.87,38.1 65.41,34.29 IC8.9
  Bottom 0.406: IC4.15 38.1,85.09 38.1,68.58 35.56,64.77 35.56,62.23 36.83,60.96 36.83,43.81 40.64,39.37 IC7.7
TDAL7
  Top 0.406: IC8.12 64.77,41.91 62.23,43.18 56.52,43.18 55.25,41.91 53.34,41.91 52.07,43.18 47.63,43.18 45.09,46.99 IC7.4
  Bottom 0.406: IC7.4 40.64,46.99 39.37,48.26 39.37,90.17 IC4.17
TDAL15  (via drill 0.61)
  Top 0.406: IC8.4 55.25,44.45 v54.61,43.81
  Bottom 0.406: IC9.13 52.07,21.59 52.07,25.4 50.8,26.67 50.8,31.75 54.61,34.29 v54.61,43.81
TSB
  Top 0.406: IC20.36 98.43,77.47 99.06,76.83 TSB.2
TX+
  Bottom 0.406: CL4.2 201.93,12.7 201.93,46.35 196.22,46.35 196.22,49.53 200.66,52.07 200.66,57.15 199.39,59.69 199.39,76.2 SV1.18
  Bottom 0.635: SV1.18 190.5,76.2 R24.2
TX-
  Bottom 0.406: SV1.19 198.12,73.66 198.12,57.78 196.22,54.61 191.77,54.61 191.77,49.53 193.04,48.26 193.04,25.4 IC29.5 200.66,25.4 200.66,13.97 Q2.1 D2.C
TXD  (via drill 0.61)
  Top 0.406: v177.8,86.36 171.45,86.36 169.55,88.27 169.55,89.53 168.91,90.17 IC24.5 164.47,90.17 164.47,83.82 160.02,83.82 159.39,83.19 146.69,83.19 145.42,85.09 IC26.8 | v179.07,35.56 179.07,33.02 185.42,25.4 IC29.2
  Bottom 0.406: v177.8,86.36 177.8,78.74 184.15,78.74 184.15,69.85 177.8,69.85 177.8,45.72 179.07,44.45 v179.07,35.56 | IC24.5 IC24.4
TXEIA\
  Top 0.406: SV1.11 186.69,93.98 185.42,92.71 185.42,87 C1.1 169.55,82.55 169.55,86.36 168.91,87.63 IC24.6
V3
  Top 0.406: IC6.5 57.15,69.85 55.25,69.22 V3.2
  Bottom 0.406: R16.2 V3.2
V4
  Bottom 0.406: IC6.11 71.12,67.31 R17.2 71.12,56.52 V4.2
V5
  Bottom 0.406: V5.2 67.95,82.55 72.39,82.55 R18.2 IC6.14
V6
  Top 0.406: IC7.5 39.37,44.45 38.1,46.99 V6.2
  Bottom 0.406: V6.2 R14.2
V7
  Top 0.406: R15.2 IC7.2
  Bottom 0.406: R15.2 V7.2
VCC  (via drill 0.61, 0.81)
  Top 0.406: IC15.2 170.18,21.59 172.09,19.05 IC15.12
  Top 0.635: EDGE$.BV1 19.97,127.88 21.38,129.12 29.51,129.12 31.45,127 IC1.20 | v64.77,58.42 R17.1 60.96,57.15 58.42,54.61 IC7.16 | IC4.20 38.1,97.79 40.64,99.69 50.8,99.69 IC3.20 | IC20.34 97.79,72.39 99.06,71.12 v111.76,71.12 | R18.1 73.66,85.09 77.47,87.63 IC20.1 v85.09,87.63 | IC2.20 36.83,31.75 38.74,31.11 46.99,31.11 v47.63,30.48 | IC11.14 95.25,24.13 95.89,24.77 98.43,24.77 99.7,23.5 106.05,23.5 109.22,26.04 119.38,26.04 | 119.38,26.04 137.16,26.04 IC13.14 146.05,24.13 147.96,26.04 157.48,26.04 | 119.38,26.04 IC12.14 | 157.48,26.04 173.99,26.04 IC15.14 184.15,24.13 R8.1 | 157.48,26.04 IC14.14 | IC26.14 IC25.1 | IC16.2 168.91,52.07 171.45,54.61 IC16.14 | v166.37,104.14 169.55,104.14 171.45,101.6 171.45,91.44 172.72,90.17 IC24.10 | IC13.4 130.81,15.24 134.62,15.24 135.89,13.97 IC13.10 | IC17.1 IC17.14 IC17.13 | IC22.10 154.94,67.31 149.86,69.85 IC22.4 | IC27.4 143.51,117.47 143.51,125.09 IC27.16
  Bottom 0.635: 64.77,80.01 IC6.16 | 48.26,97.79 IC3.20 | 48.26,66.67 48.26,97.79 | 48.26,66.67 R16.1 | 48.26,97.79 48.26,102.87 | 48.26,102.87 48.26,104.14 55.88,104.14 R26.1 R25.1 R23.1 R21.1 R19.1 55.88,128.27 86.36,128.27 | R32.1 R29.1 R28.1 R27.1 R31.1 102.87,128.27 97.79,128.27 | 86.36,128.27 97.79,128.27 | 86.36,128.27 IC5.24 | R18.1 69.85,88.9 64.77,88.9 64.77,80.01 | 64.77,80.01 v64.77,58.42 67.31,57.15 IC8.16 65.41,52.07 65.41,24.13 IC10.14 R41.2 | IC1.20 36.83,127 36.83,119.38 | 36.83,114.3 36.83,97.79 IC4.20 31.75,97.79 31.75,52.07 R15.1 R14.1 | 36.83,114.3 36.83,119.38 | 153.67,100.33 IC25.14 C14.1 162.56,100.33 v166.37,104.14 | IC25.1 153.67,100.33 | IC7.16 47.63,54.61 | 47.63,54.61 47.63,45.72 46.36,44.45 46.36,33.66 v47.63,30.48 47.63,24.13 | 48.26,66.67 47.63,66.67 47.63,54.61 | EDGE$.AA2 13.97,3.81 R34.1 47.63,3.81 47.63,24.13 | 47.63,24.13 IC9.14 | v85.09,87.63 85.09,40.64 88.9,36.83 88.9,24.13 IC11.14 | 114.3,48.26 IC19.5 | 114.3,53.34 114.3,62.23 C11.+ 113.67,71.12 | 114.3,53.34 114.3,48.26 | 113.67,71.12 v113.67,74.3 v113.67,76.83 v113.67,79.38 v113.67,81.92 v113.67,84.45 113.67,101.6 97.79,101.6 97.79,128.27 | 134.62,55.88 134.62,39.37 137.16,36.83 IC13.14 134.62,24.13 134.62,13.97 IC13.10 | 134.62,55.88 IC18.14 | 134.62,77.47 IC21.14 | 134.62,77.47 134.62,55.88 | 134.62,81.28 134.62,100.33 IC26.14 143.51,104.14 143.51,122.56 | 134.62,81.28 134.62,77.47 | 153.67,100.33 153.67,82.55 C10.+ IC22.14 154.31,77.47 154.31,67.31 | 154.31,54.61 IC17.14 | 154.31,67.31 154.31,54.61 | IC27.16 143.51,125.09 143.51,122.56 | R8.1 184.15,20.95 190.5,20.95 190.5,32.38 186.69,32.38 183.52,34.92 183.52,41.91 186.06,44.45 R6.1
  Bottom 0.635: 171.45,77.47 171.45,54.61 | 171.45,77.47 171.45,87.63 IC24.9 IC24.10 | 171.45,54.61 171.45,27.94 C9.+ IC15.14 172.09,24.13 172.09,19.05 | 171.45,54.61 IC16.14 IC16.13 | 171.45,77.47 IC23.14 | 114.3,48.26 114.3,38.1 110.49,31.75 110.49,26.67 106.68,22.86 101.6,22.86 C13.+ | 48.26,102.87 C15.+ | 113.67,71.12 v111.76,71.12 | 154.31,54.61 154.31,26.04 157.48,26.04 IC14.14 | 134.62,81.28 C20.+ | 36.83,114.3 IC1.15 | 36.83,119.38 IC1.17 | IC15.10 172.09,13.97 172.09,19.05 | 172.09,19.05 IC15.12 | 154.31,67.31 IC22.10 | 114.3,53.34 IC19.3 | 143.51,122.56 IC27.15
XBUF\  (via drill 0.61)
  Top 0.406: IC18.8 134.62,40.64 131.45,37.47 110.49,37.47 109.22,36.83 v99.06,36.83
  Bottom 0.406: v99.06,36.83 99.06,43.18 97.79,44.45 IC20.23
XCSR  (via drill 0.61)
  Top 0.406: IC22.11 158.75,69.85 160.02,68.58 v161.29,68.58 | IC13.11 132.08,16.51 131.45,17.78 127.64,17.78 127.64,12.7 116.84,12.7 115.57,11.43 IC12.6 | v142.24,58.42 v162.56,58.42
  Bottom 0.406: IC13.11 140.97,16.51 140.97,30.48 142.24,31.75 v142.24,58.42 | v162.56,58.42 162.56,67.31 v161.29,68.58
XDATA0  (via drill 0.61)
  Top 0.406: IC20.25 v105.41,49.53 | IC26.9 134.62,87.63 133.35,88.9 128.27,88.9 125.73,86.36 v104.14,86.36
  Bottom 0.406: v105.41,49.53 105.41,62.23 106.68,66.04 106.68,69.85 104.14,72.39 v104.14,86.36
XIAKI\
  Bottom 0.406: IC15.1 163.83,24.13 163.83,4.45 | 163.83,4.45 80.65,4.45 80.65,13.97 IC11.5 | 163.83,4.45 177.8,4.45 177.8,19.68 179.07,21.59 179.07,33.02 173.99,33.02 173.99,38.1 | 173.99,38.1 173.99,38.73 | 173.99,38.1 IC16.8
XIE  (via drill 0.61)
  Top 0.406: v142.24,22.86 143.51,21.59 IC14.2 | v133.35,36.83 132.08,36.2 111.76,36.2 109.22,34.92 88.9,34.92 87,36.2 84.46,36.2 81.92,34.92 76.84,34.92 75.57,33.66 70.49,33.66 69.85,36.83 IC8.10
  Bottom 0.406: 139.7,11.43 138.43,11.43 | 139.7,11.43 142.24,11.43 v142.24,22.86 | 139.7,11.43 IC13.9 134.62,11.43 | 134.62,11.43 133.35,11.43 v133.35,36.83 133.35,92.71 IC26.4 | 134.62,11.43 136.53,11.43
XIRQ
  Top 0.406: IC16.9 171.45,41.91 170.18,40.64 165.1,40.64 163.83,39.37 IC17.8
XIRQ\  (via drill 0.61)
  Top 0.406: IC11.2 86.36,21.59 87.63,22.86 v96.52,22.86 | v104.78,46.35 105.41,46.99 114.3,46.99 116.84,49.53 125.73,49.53 127,54.61 132.08,54.61 133.35,53.34 IC18.13 143.51,53.34 146.05,45.72 150.5,45.72 154.31,41.91 IC17.9 | v57.15,32.38 76.2,32.38 77.47,33.66 83.82,33.66 v84.46,34.29
  Bottom 0.406: IC11.2 81.28,21.59 81.28,33.66 83.82,33.66 v84.46,34.29 | IC6.2 57.15,77.47 v57.15,32.38 | v96.52,22.86 96.52,25.4 102.87,31.75 102.87,42.55 104.78,45.09 v104.78,46.35
XRDY
  Top 0.406: IC15.9 171.45,11.43 171.45,17.14 168.91,20.32 163.83,20.32 163.83,21.59 IC14.13
XRDY0  (via drill 0.61)
  Top 0.406: v105.41,40.64 99.06,40.64 97.16,41.91 IC20.22 93.35,40.64 77.47,40.64 77.47,44.45 IC8.13 | v106.68,88.27 124.46,88.27 126.37,90.17 IC26.5
  Bottom 0.406: v105.41,40.64 105.41,41.91 106.68,43.18 106.68,62.23 107.95,66.04 107.95,71.12 106.68,72.39 v106.68,88.27
XRDYI  (via drill 0.61)
  Top 0.406: IC14.1 152.4,24.13 v153.67,22.86 170.82,22.86 172.72,20.32 176.53,20.32 176.53,16.51 IC15.11 | IC26.6 132.08,87.63 133.35,86.36 133.35,83.19 143.51,83.19 146.69,79.38 150.5,79.38 v152.4,80.01
  Bottom 0.406: v153.67,22.86 153.04,23.5 153.04,80.01 v152.4,80.01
